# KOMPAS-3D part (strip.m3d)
File: created 18.09.2016 11:49:25, last saved 05.10.2016 12:24:00.
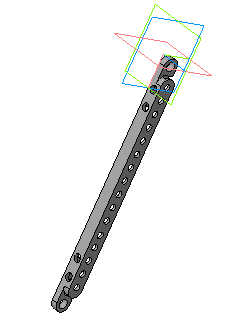
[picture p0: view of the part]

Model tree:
1. Эскиз:1
2. Операция выдавливания:1
     Расстояние 1 = 5
3. Эскиз:2
4. Операция выдавливания:2
     Расстояние 1 = 5
5. Эскиз:3
6. Вырезать элемент выдавливания:1
     Расстояние 2 = 9; Расстояние 1 = 9
7. Эскиз:4
8. Вырезать элемент выдавливания:2
     Расстояние 2 = 9; Расстояние 1 = 9
9. Эскиз:5
10. Вырезать элемент выдавливания:3
     Расстояние 2 = 9; Расстояние 1 = 19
